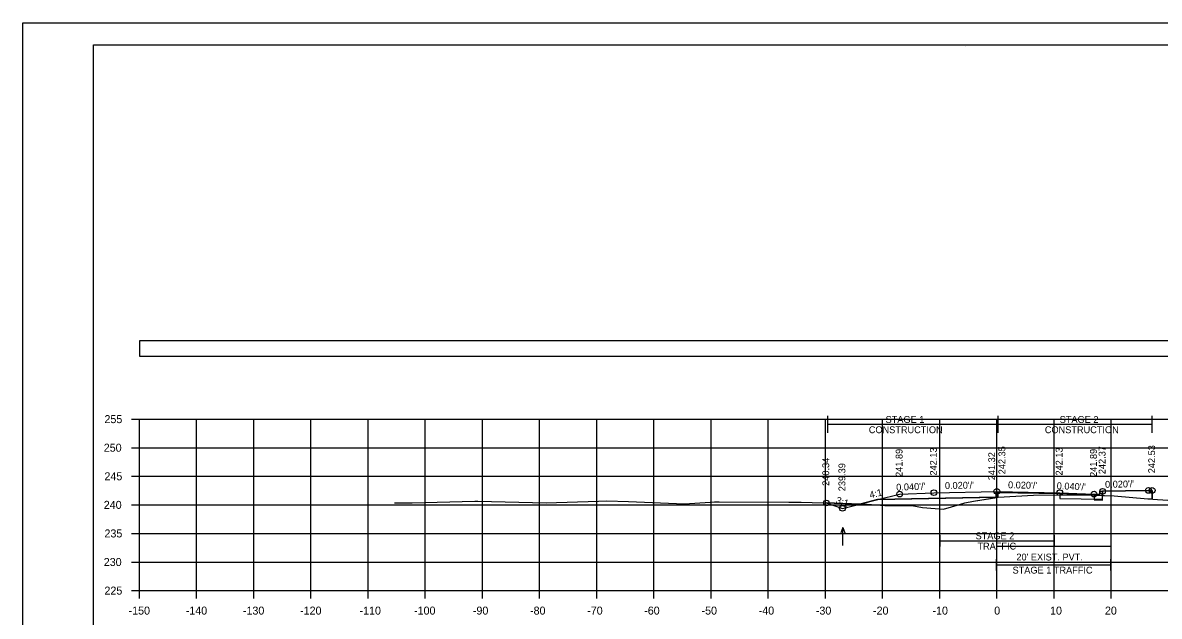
# Model space of a CAD drawing. Extents: x 1369627 to 1374022, y 380035 to 398173.
# Drawn here: x 1370008.8 to 1370207.7, y 380144.4 to 380248.2 of the extents above; entities that cross this region are included whole.
import ezdxf

# ---------------------------------------------------------------- set-up
doc = ezdxf.new("R2010")
doc.units = 0
for name, color, linetype in [('Default', 7, 'Continuous'), ('R_Alt Surface', 7, 'Continuous'), ('R_Axis', 7, 'Continuous'), ('R_Axis Annot', 7, 'Continuous'), ('R_Border', 7, 'Continuous'), ('R_Exist Surface', 7, 'Continuous'), ('R_Fin Surface', 7, 'Continuous'), ('R_Grid', 7, 'Continuous'), ('R_MOT', 7, 'Continuous'), ('R_No Plot', 7, 'Continuous'), ('R_Water Annot', 7, 'Continuous'), ('R_Xsect Elev', 7, 'Continuous'), ('R_Xsect Slope', 7, 'Continuous'), ('T_Vehicle Path Rt', 7, 'Continuous')]:
    doc.layers.add(name, color=color, linetype=linetype)

msp = doc.modelspace()

# ---------------------------------------------------------------- linework, layer by layer
at = {"layer": 'Default'}
msp.add_lwpolyline([(1370029.24, 380189.87), (1370329.24, 380189.87), (1370329.24, 380192.57), (1370029.24, 380192.57)], close=True, dxfattribs=at)
at = {"layer": 'R_Alt Surface'}
msp.add_lwpolyline([(1370158.38, 380164.79), (1370179.15, 380165.21), (1370179.15, 380166.04), (1370179.24, 380166.04), (1370190.24, 380165.82), (1370196.24, 380165.58), (1370196.24, 380164.75), (1370197.74, 380164.71), (1370197.74, 380166.23)], dxfattribs=at)
at = {"layer": 'R_Axis'}
for p, q in [((1370027.84, 380178.86), (1370029.24, 380178.86)), ((1370029.24, 380148.86), (1370029.24, 380178.86)), ((1370027.84, 380173.86), (1370029.24, 380173.86)), ((1370027.84, 380168.86), (1370029.24, 380168.86)), ((1370027.84, 380163.86), (1370029.24, 380163.86)), ((1370027.84, 380158.86), (1370029.24, 380158.86)), ((1370027.84, 380153.86), (1370029.24, 380153.86)), ((1370027.84, 380148.86), (1370029.24, 380148.86)), ((1370029.24, 380148.86), (1370329.24, 380148.86)), ((1370029.24, 380147.46), (1370029.24, 380148.86)), ((1370039.24, 380147.46), (1370039.24, 380148.86)), ((1370049.24, 380147.46), (1370049.24, 380148.86)), ((1370059.24, 380147.46), (1370059.24, 380148.86)), ((1370069.24, 380147.46), (1370069.24, 380148.86)), ((1370079.24, 380147.46), (1370079.24, 380148.86)), ((1370089.24, 380147.46), (1370089.24, 380148.86)), ((1370099.24, 380147.46), (1370099.24, 380148.86)), ((1370109.24, 380147.46), (1370109.24, 380148.86)), ((1370119.24, 380147.46), (1370119.24, 380148.86)), ((1370129.24, 380147.46), (1370129.24, 380148.86)), ((1370139.24, 380147.46), (1370139.24, 380148.86)), ((1370149.24, 380147.46), (1370149.24, 380148.86)), ((1370159.24, 380147.46), (1370159.24, 380148.86)), ((1370169.24, 380147.46), (1370169.24, 380148.86)), ((1370179.24, 380147.46), (1370179.24, 380148.86)), ((1370189.24, 380147.46), (1370189.24, 380148.86)), ((1370199.24, 380147.46), (1370199.24, 380148.86))]:
    msp.add_line(p, q, dxfattribs=at)
at = {"layer": 'R_Border'}
for p, q in [((1370021.24, 380244.32), (1370337.42, 380244.32)), ((1370021.24, 380038.86), (1370021.24, 380244.32)), ((1370173.76, 380244.06), (1370173.76, 380244.06)), ((1370173.76, 380244.06), (1370173.76, 380244.06))]:
    msp.add_line(p, q, dxfattribs=at)
at = {"layer": 'R_Exist Surface'}
msp.add_lwpolyline([(1370073.86, 380164.24), (1370076.94, 380164.23), (1370087.92, 380164.51), (1370088.28, 380164.52), (1370088.44, 380164.52), (1370100.39, 380164.19), (1370109.56, 380164.52), (1370110.99, 380164.54), (1370114.82, 380164.44), (1370124.62, 380164.06), (1370129.11, 380164.36), (1370129.82, 380164.4), (1370130.65, 380164.41), (1370142.85, 380164.36), (1370145.02, 380164.34), (1370156.53, 380163.96), (1370159.67, 380163.77), (1370164.36, 380163.73), (1370166.25, 380163.41), (1370169.92, 380163.12), (1370172.72, 380163.94), (1370173.63, 380164.19), (1370175.15, 380164.48), (1370179.49, 380165.22), (1370185.68, 380165.53), (1370189.15, 380165.64), (1370196.37, 380165.55), (1370199.79, 380165.44), (1370205.63, 380164.94), (1370207.33, 380164.82), (1370210.06, 380164.64)], dxfattribs=at)
at = {"layer": 'R_Fin Surface'}
msp.add_lwpolyline([(1370149.41, 380164.19), (1370152.24, 380163.25), (1370158.4, 380164.79), (1370162.24, 380165.75), (1370168.24, 380165.99), (1370179.24, 380166.21), (1370190.24, 380165.99), (1370196.24, 380165.75), (1370197.24, 380165.73), (1370197.25, 380166.23), (1370197.75, 380166.23), (1370205.75, 380166.39), (1370206.42, 380166.39), (1370206.42, 380164.89)], dxfattribs=at)
at = {"layer": 'R_Grid'}
for p, q in [((1370029.24, 380178.86), (1370329.24, 380178.86)), ((1370029.24, 380148.86), (1370029.24, 380178.86)), ((1370039.24, 380148.86), (1370039.24, 380178.86)), ((1370049.24, 380148.86), (1370049.24, 380178.86)), ((1370059.24, 380148.86), (1370059.24, 380178.86)), ((1370069.24, 380148.86), (1370069.24, 380178.86)), ((1370079.24, 380148.86), (1370079.24, 380178.86)), ((1370089.24, 380148.86), (1370089.24, 380178.86)), ((1370099.24, 380148.86), (1370099.24, 380178.86)), ((1370109.24, 380148.86), (1370109.24, 380178.86)), ((1370119.24, 380148.86), (1370119.24, 380178.86)), ((1370129.24, 380148.86), (1370129.24, 380178.86)), ((1370139.24, 380148.86), (1370139.24, 380178.86)), ((1370149.24, 380148.86), (1370149.24, 380178.86)), ((1370159.24, 380148.86), (1370159.24, 380178.86)), ((1370169.24, 380148.86), (1370169.24, 380178.86)), ((1370179.24, 380148.86), (1370179.24, 380178.86)), ((1370189.24, 380148.86), (1370189.24, 380178.86)), ((1370199.24, 380148.86), (1370199.24, 380178.86)), ((1370029.24, 380173.86), (1370329.24, 380173.86)), ((1370029.24, 380168.86), (1370329.24, 380168.86)), ((1370029.24, 380163.86), (1370329.24, 380163.86)), ((1370029.24, 380158.86), (1370329.24, 380158.86)), ((1370029.24, 380153.86), (1370329.24, 380153.86)), ((1370029.24, 380148.86), (1370329.24, 380148.86))]:
    msp.add_line(p, q, dxfattribs=at)
at = {"layer": 'R_MOT'}
for p, q in [((1370149.67, 380176.45), (1370149.67, 380179.45)), ((1370179.49, 380176.45), (1370179.49, 380179.45)), ((1370206.42, 380176.45), (1370206.42, 380179.45)), ((1370149.67, 380177.95), (1370206.42, 380177.95)), ((1370169.24, 380158.58), (1370169.24, 380156.58)), ((1370189.24, 380158.58), (1370189.24, 380156.58)), ((1370169.24, 380157.58), (1370189.24, 380157.58)), ((1370179.15, 380154.37), (1370179.15, 380152.37)), ((1370199.15, 380154.37), (1370199.15, 380152.37)), ((1370179.15, 380153.37), (1370199.15, 380153.37))]:
    msp.add_line(p, q, dxfattribs=at)
at = {"layer": 'R_No Plot'}
for p, q in [((1370008.84, 380248.21), (1370342.17, 380248.21)), ((1370179.24, 380165.21), (1370179.49, 380165.2)), ((1370179.49, 380165.2), (1370179.49, 380166.04)), ((1370179.49, 380166.04), (1370190.24, 380165.82)), ((1370190.24, 380165.82), (1370190.24, 380164.99)), ((1370190.24, 380164.99), (1370197.75, 380164.84)), ((1370197.75, 380164.84), (1370197.75, 380166.23))]:
    msp.add_line(p, q, dxfattribs=at)
for points in [[(1370008.83, 380248.21), (1370342.17, 380248.21), (1370342.17, 380034.87), (1370008.83, 380034.87)], [(1370255.16, 380244.32), (1370274.78, 380244.32), (1370274.78, 380234.44), (1370290.89, 380234.44), (1370314.09, 380234.44), (1370314.09, 380201.77), (1370337.3, 380201.77), (1370337.42, 380038.86), (1370021.24, 380038.86), (1370021.24, 380244.32)]]:
    msp.add_lwpolyline(points, close=True, dxfattribs=at)
for points in [[(1370158.4, 380164.79), (1370179.24, 380165.21)], [(1370179.15, 380156.64), (1370199.15, 380156.64)]]:
    msp.add_lwpolyline(points, dxfattribs=at)
for centre in [(1370168.24, 380165.99), (1370179.24, 380166.21), (1370190.24, 380165.99), (1370197.75, 380166.23), (1370205.75, 380166.39), (1370206.42, 380166.39), (1370149.41, 380164.19), (1370162.24, 380165.75), (1370196.24, 380165.75), (1370152.24, 380163.25)]:
    msp.add_circle(centre, 0.5, dxfattribs=at)
at = {"layer": 'R_Water Annot'}
for p, q in [((1370152.29, 380159.9), (1370151.94, 380158.94)), ((1370152.29, 380156.76), (1370152.29, 380159.9)), ((1370152.29, 380159.9), (1370152.64, 380158.94))]:
    msp.add_line(p, q, dxfattribs=at)
at = {"layer": 'R_Xsect Elev'}
msp.add_line((1370179.24, 380165.17), (1370179.24, 380175.17), dxfattribs=at)
at = {"layer": 'T_Vehicle Path Rt'}
for p, q in [((1370179.15, 380165.2), (1370179.24, 380165.21)), ((1370179.24, 380165.21), (1370179.15, 380165.21)), ((1370179.24, 380166.04), (1370179.24, 380165.21)), ((1370179.24, 380165.21), (1370179.24, 380166.04)), ((1370179.24, 380165.21), (1370179.24, 380165.17)), ((1370179.4, 380165.2), (1370179.24, 380165.21)), ((1370179.24, 380165.21), (1370179.4, 380165.2)), ((1370179.24, 380165.17), (1370179.24, 380165.21)), ((1370179.24, 380165.17), (1370179.4, 380165.2)), ((1370179.49, 380165.22), (1370179.4, 380165.2)), ((1370179.4, 380165.2), (1370179.49, 380165.22)), ((1370179.4, 380165.2), (1370179.49, 380165.2)), ((1370179.49, 380165.2), (1370179.49, 380165.22)), ((1370196.24, 380165.55), (1370196.24, 380165.58)), ((1370197.75, 380166.23), (1370197.75, 380165.51)), ((1370197.75, 380165.51), (1370199.79, 380165.44)), ((1370155.26, 380164), (1370149.41, 380164.19))]:
    msp.add_line(p, q, dxfattribs=at)
for points in [[(1370206.42, 380164.89), (1370206.42, 380166.39), (1370205.75, 380166.39), (1370197.75, 380166.23)], [(1370155.26, 380164), (1370156.53, 380163.96), (1370159.67, 380163.77), (1370164.36, 380163.73), (1370166.25, 380163.41), (1370169.92, 380163.12), (1370172.72, 380163.94), (1370173.63, 380164.19), (1370175.15, 380164.48), (1370179.24, 380165.17)], [(1370158.38, 380164.79), (1370158.38, 380164.79), (1370155.26, 380164)], [(1370179.15, 380165.21), (1370158.4, 380164.79), (1370158.38, 380164.79)], [(1370179.24, 380166.04), (1370179.15, 380166.04), (1370179.15, 380165.21)], [(1370179.15, 380165.21), (1370179.15, 380165.2)], [(1370196.24, 380165.58), (1370190.24, 380165.82), (1370179.24, 380166.04)], [(1370179.49, 380165.22), (1370185.68, 380165.53), (1370189.15, 380165.64), (1370196.24, 380165.55)], [(1370197.74, 380165.51), (1370196.37, 380165.55), (1370196.24, 380165.55)], [(1370196.24, 380165.55), (1370196.24, 380164.75), (1370197.74, 380164.71), (1370197.74, 380165.51), (1370197.74, 380165.51)], [(1370199.79, 380165.44), (1370205.63, 380164.94), (1370206.42, 380164.89)], [(1370149.41, 380164.19), (1370152.24, 380163.25), (1370155.26, 380164)]]:
    msp.add_lwpolyline(points, dxfattribs=at)

# ---------------------------------------------------------------- texts
at = {"layer": 'R_Axis Annot'}
for s, height, p in [('255', 1.4, (1370023.13, 380178.16)), ('250', 1.4, (1370023.01, 380173.16)), ('245', 1.4, (1370023.13, 380168.16)), ('240', 1.4, (1370023.01, 380163.16)), ('235', 1.4, (1370023.13, 380158.16)), ('230', 1.4, (1370023.01, 380153.16)), ("20' EXIST. PVT.", 1.2, (1370182.66, 380154.13)), ('225', 1.4, (1370023.13, 380148.16)), ('-150', 1.4, (1370027.35, 380144.66)), ('-140', 1.4, (1370037.35, 380144.66)), ('-130', 1.4, (1370047.35, 380144.66)), ('-120', 1.4, (1370057.35, 380144.66)), ('-110', 1.4, (1370067.75, 380144.66)), ('-100', 1.4, (1370077.29, 380144.66)), ('-90', 1.4, (1370087.58, 380144.66)), ('-80', 1.4, (1370097.58, 380144.66)), ('-70', 1.4, (1370107.58, 380144.66)), ('-60', 1.4, (1370117.55, 380144.66)), ('-50', 1.4, (1370127.58, 380144.66)), ('-40', 1.4, (1370137.58, 380144.66)), ('-30', 1.4, (1370147.58, 380144.66)), ('-20', 1.4, (1370157.58, 380144.66)), ('-10', 1.4, (1370167.98, 380144.66)), ('0', 1.4, (1370178.78, 380144.66)), ('10', 1.4, (1370188.55, 380144.66)), ('20', 1.4, (1370198.15, 380144.66))]:
    msp.add_text(s, height=height, dxfattribs=at).set_placement(p)
at = {"layer": 'R_MOT'}
for s, p in [('STAGE 1', (1370159.78, 380178.2)), ('STAGE 2', (1370190.24, 380178.2)), ('CONSTRUCTION', (1370156.84, 380176.4)), ('CONSTRUCTION', (1370187.64, 380176.4)), ('STAGE 2', (1370175.52, 380157.84)), ('TRAFFIC', (1370175.85, 380156.04)), ('STAGE 1 TRAFFIC', (1370181.99, 380151.84))]:
    msp.add_text(s, height=1.2, dxfattribs=at).set_placement(p)
at = {"layer": 'R_Xsect Elev'}
for s, p in [('242.53', (1370206.92, 380169.39)), ('241.89', (1370162.74, 380168.75)), ('242.13', (1370168.74, 380168.99)), ('241.32', (1370178.94, 380168.17)), ('242.35', (1370180.73, 380169.21)), ('242.13', (1370190.74, 380168.99)), ('241.89', (1370196.74, 380168.75)), ('242.37', (1370198.25, 380169.23)), ('240.34', (1370149.91, 380167.19)), ('239.39', (1370152.74, 380166.25))]:
    msp.add_text(s, height=1.2, rotation=90, dxfattribs=at).set_placement(p)
at = {"layer": 'R_Xsect Slope'}
for s, rotation, p in [('4:1', 14.0362, (1370157.12, 380164.99)), ("0.040'/'", 2.2906, (1370161.66, 380166.33)), ("0.020'/'", 1.1458, (1370170.17, 380166.63)), ("0.020'/'", 358.8542, (1370181.19, 380166.77)), ("0.040'/'", 357.7094, (1370189.7, 380166.61)), ("0.020'/'", 1.1458, (1370198.18, 380166.84)), ('3:1', 341.5651, (1370150.98, 380164.2))]:
    msp.add_text(s, height=1.2, rotation=rotation, dxfattribs=at).set_placement(p)

doc.saveas('drawing.dxf')
